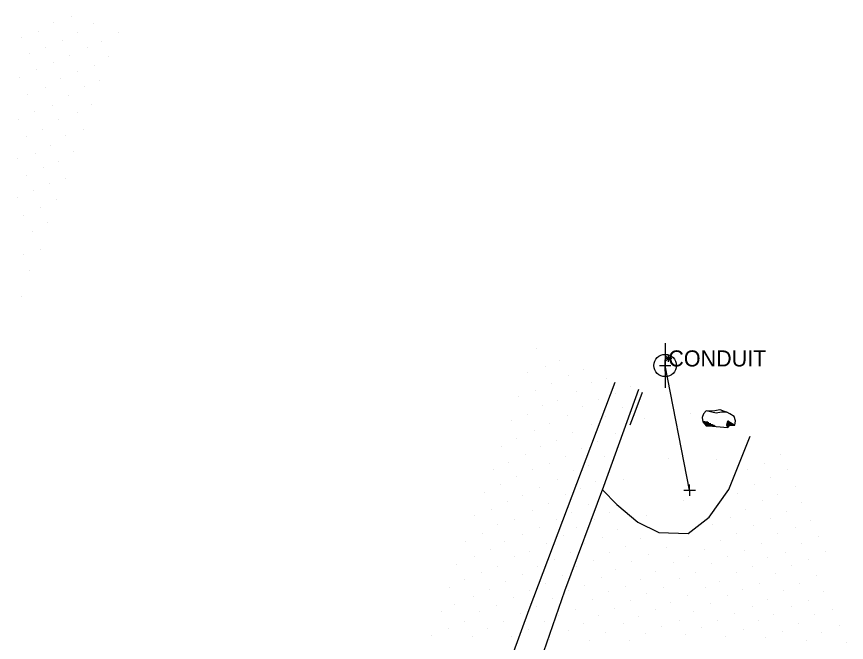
# Model space of a CAD drawing. Extents: x 1729983 to 1730242, y 468641 to 469019.
# Drawn here: x 1730133.1 to 1730225.9, y 468949.2 to 469019.2 of the extents above; entities that cross this region are included whole.
import ezdxf

# ---------------------------------------------------------------- set-up
doc = ezdxf.new("R2010")
doc.units = 0
for name, color, linetype in [('Default', 7, 'Continuous'), ('S_Curb_Type_1', 7, 'Continuous'), ('S_Ground_SpotElevation', 7, 'Continuous'), ('S_Misc_MiscItems', 7, 'Continuous'), ('S_Property_RockBoulder', 7, 'Continuous'), ('S_Roadway_Drive_Paved', 7, 'Continuous'), ('S_Roadway_Edge_Pavement', 7, 'Continuous'), ('S_Roadway_Painted_Lines', 7, 'Continuous'), ('S_Survey_Shot', 7, 'Continuous'), ('S_Text', 7, 'Continuous'), ('S_Utilities_GuyWire3', 7, 'Continuous'), ('S_Utilities_Pole_Power', 7, 'Continuous')]:
    doc.layers.add(name, color=color, linetype=linetype)

# ---------------------------------------------------------------- blocks, each defined once
blk = doc.blocks.new('POINT_DISPLAY')
at = {"layer": 'Default'}
blk.add_line((0, 0), (0, 0), dxfattribs=at)

msp = doc.modelspace()

# ---------------------------------------------------------------- linework, layer by layer
at = {"layer": 'S_Curb_Type_1'}
msp.add_lwpolyline([(1730201.693, 468973.575), (1730202.263, 468975.004), (1730203.086, 468977.205)], dxfattribs=at)
at = {"layer": 'S_Misc_MiscItems'}
for p, q in [((1730206.362, 468980.991), (1730205.576, 468980.991)), ((1730206.231, 468980.729), (1730205.707, 468981.253)), ((1730206.231, 468981.253), (1730205.707, 468980.729)), ((1730205.969, 468981.384), (1730205.969, 468980.598))]:
    msp.add_line(p, q, dxfattribs=at)
at = {"layer": 'S_Property_RockBoulder'}
for p, q in [((1730209.957, 468973.912), (1730210.387, 468973.912)), ((1730209.99, 468973.953), (1730209.99, 468973.83)), ((1730210.038, 468973.823), (1730210.505, 468973.823)), ((1730210.086, 468973.946), (1730210.086, 468973.685)), ((1730210.128, 468973.707), (1730210.732, 468973.707)), ((1730210.189, 468973.59), (1730210.903, 468973.59)), ((1730210.203, 468973.946), (1730210.203, 468973.576)), ((1730210.279, 468973.48), (1730211.123, 468973.48)), ((1730210.326, 468973.946), (1730210.326, 468973.432)), ((1730210.438, 468973.858), (1730210.438, 468973.439)), ((1730210.533, 468973.747), (1730210.533, 468973.452)), ((1730210.642, 468973.727), (1730210.642, 468973.432)), ((1730210.76, 468973.637), (1730210.76, 468973.432)), ((1730210.862, 468973.603), (1730210.862, 468973.405)), ((1730211.013, 468973.548), (1730211.013, 468973.405)), ((1730211.137, 468973.487), (1730211.137, 468973.425)), ((1730212.536, 468973.535), (1730212.64, 468973.727)), ((1730212.536, 468973.535), (1730212.64, 468973.582)), ((1730212.536, 468973.535), (1730212.64, 468973.527)), ((1730212.536, 468973.535), (1730212.64, 468973.432)), ((1730212.64, 468974.008), (1730212.852, 468973.535)), ((1730212.64, 468974.008), (1730213.29, 468973.535)), ((1730212.64, 468974.008), (1730213.119, 468973.535)), ((1730212.64, 468974.008), (1730212.955, 468973.535)), ((1730212.64, 468974.008), (1730212.792, 468973.463)), ((1730212.64, 468974.008), (1730212.753, 468973.414)), ((1730212.64, 468974.008), (1730212.64, 468973.274))]:
    msp.add_line(p, q, dxfattribs=at)
for points in [[(1730210.216, 468975.119), (1730211.164, 468975.168), (1730211.741, 468975.278), (1730212.536, 468974.962)], [(1730210.477, 468973.432), (1730212.64, 468973.274), (1730212.852, 468973.535), (1730213.429, 468973.535), (1730213.484, 468974.008), (1730213.325, 468974.481), (1730212.852, 468974.797), (1730212.536, 468974.962), (1730211.904, 468974.962), (1730211.321, 468974.852), (1730210.848, 468974.962), (1730210.216, 468975.119), (1730209.902, 468974.797), (1730209.743, 468974.379), (1730209.847, 468973.905), (1730210.216, 468973.432), (1730210.477, 468973.432)], [(1730212.64, 468973.274), (1730212.536, 468973.535), (1730212.64, 468974.008), (1730213.429, 468973.535)]]:
    msp.add_lwpolyline(points, dxfattribs=at)
at = {"layer": 'S_Roadway_Drive_Paved'}
msp.add_lwpolyline([(1730198.596, 468966.276), (1730200.222, 468964.652), (1730202.566, 468962.674), (1730204.922, 468961.527), (1730208.207, 468961.4), (1730210.542, 468963.235), (1730212.73, 468966.337), (1730215.136, 468972.288)], dxfattribs=at)
at = {"layer": 'S_Roadway_Edge_Pavement'}
msp.add_lwpolyline([(1730202.631, 468977.503), (1730198.74, 468966.662), (1730194.376, 468954.956), (1730192.027, 468948.149), (1730189.862, 468942.05), (1730183.636, 468926), (1730174.834, 468902.219), (1730173.778, 468899.255), (1730172.823, 468896.553), (1730172.2, 468894.754), (1730169.443, 468886.971), (1730164.503, 468873.715)], dxfattribs=at)
at = {"layer": 'S_Roadway_Painted_Lines'}
msp.add_lwpolyline([(1730094.799, 468656.256), (1730095.17, 468660.96), (1730096.083, 468669.985), (1730097.638, 468680.767), (1730099.581, 468691.95), (1730101.134, 468699.687), (1730104.772, 468714.073), (1730108.651, 468727.01), (1730112.542, 468738.83), (1730119.789, 468759.429), (1730137.203, 468807.807), (1730148.896, 468839.717), (1730160.486, 468871.271), (1730175.799, 468912.851), (1730190.41, 468952.883), (1730200.037, 468978.351)], dxfattribs=at)
at = {"layer": 'S_Survey_Shot'}
for p, q in [((1730205.619, 468979.565), (1730205.617, 468980.837)), ((1730204.982, 468980.2), (1730206.254, 468980.202)), ((1730205.618, 468980.201), (1730205.618, 468980.201)), ((1730208.361, 468965.624), (1730208.359, 468966.896)), ((1730207.724, 468966.259), (1730208.996, 468966.261)), ((1730208.36, 468966.26), (1730208.36, 468966.26))]:
    msp.add_line(p, q, dxfattribs=at)
at = {"layer": 'S_Utilities_GuyWire3'}
msp.add_lwpolyline([(1730208.36, 468966.26), (1730205.618, 468980.201)], dxfattribs=at)
at = {"layer": 'S_Utilities_Pole_Power'}
msp.add_line((1730205.618, 468982.696), (1730205.618, 468977.706), dxfattribs=at)
msp.add_circle((1730205.618, 468980.201), 1.248, dxfattribs=at)

# ---------------------------------------------------------------- block references
at = {"layer": 'S_Ground_SpotElevation'}
for p in [(1730139.207, 469019.242), (1730137.209, 469018.551), (1730141.654, 469018.42), (1730135.493, 469017.571), (1730139.866, 469017.469), (1730144.513, 469017.475), (1730133.575, 469016.937), (1730138.181, 469016.543), (1730142.598, 469016.432), (1730136.29, 469015.819), (1730140.962, 469015.812), (1730134.458, 469015.091), (1730139.017, 469014.92), (1730143.314, 469014.745), (1730135.278, 469013.283), (1730137.186, 469014.149), (1730141.791, 469013.809), (1730133.45, 469012.392), (1730139.883, 469013.123), (1730137.957, 469012.3), (1730140.652, 469011.399), (1730142.378, 469012.088), (1730134.32, 469010.53), (1730136.338, 469011.315), (1730138.88, 469010.384), (1730137.118, 469009.317), (1730141.416, 469009.4), (1730133.275, 469007.708), (1730135.075, 469008.571), (1730137.802, 469007.776), (1730139.867, 469008.493), (1730134.229, 469005.828), (1730135.963, 469006.658), (1730138.592, 469005.927), (1730140.54, 469006.57), (1730135.159, 469003.976), (1730136.846, 469004.848), (1730139.465, 469004.149), (1730133.157, 469003.359), (1730137.722, 469003.065), (1730136.052, 469002.317), (1730134.128, 469001.463), (1730136.754, 469000.594), (1730138.539, 469001.176), (1730134.949, 468999.744), (1730133.117, 468998.956), (1730137.543, 468998.786), (1730135.738, 468997.926), (1730133.851, 468997.012), (1730136.578, 468996.219), (1730134.798, 468995.159), (1730135.701, 468993.196), (1730133.829, 468992.578), (1730134.562, 468990.793), (1730133.569, 468987.92), (1730191.187, 468982.08), (1730193.833, 468980.769), (1730192.201, 468980.139), (1730190.235, 468979.389), (1730194.784, 468979.058), (1730196.535, 468979.751), (1730192.931, 468978.202), (1730197.399, 468978.296), (1730199.063, 468978.788), (1730191.104, 468977.433), (1730195.698, 468977.244), (1730200.095, 468977.11), (1730201.712, 468977.848), (1730189.222, 468976.691), (1730193.619, 468976.3), (1730198.196, 468976.419), (1730191.895, 468975.712), (1730196.421, 468975.629), (1730200.854, 468975.448), (1730190.249, 468974.73), (1730194.667, 468974.563), (1730198.977, 468974.543), (1730208.452, 468974.852), (1730188.396, 468974.062), (1730192.662, 468973.704), (1730197.363, 468973.598), (1730203.34, 468974.223), (1730191.014, 468972.918), (1730195.244, 468972.691), (1730200.02, 468972.627), (1730189.037, 468972.026), (1730193.495, 468971.794), (1730198.029, 468971.657), (1730187.275, 468971.11), (1730191.657, 468971.111), (1730196.206, 468970.884), (1730189.998, 468970.265), (1730194.48, 468970.042), (1730198.8, 468970.065), (1730205.964, 468969.752), (1730211.369, 468969.716), (1730218.469, 468970.254), (1730188.135, 468969.355), (1730192.705, 468969.282), (1730197.079, 468969.004), (1730216.75, 468969.231), (1730186.451, 468968.556), (1730188.952, 468967.805), (1730190.732, 468968.606), (1730195.343, 468968.496), (1730214.78, 468968.617), (1730219.313, 468968.542), (1730187.163, 468966.932), (1730193.57, 468967.443), (1730197.82, 468967.267), (1730200.995, 468967.489), (1730217.41, 468967.672), (1730185.464, 468965.993), (1730191.533, 468966.543), (1730196.124, 468966.415), (1730215.615, 468966.829), (1730220.204, 468966.628), (1730189.661, 468965.701), (1730194.42, 468965.745), (1730207.724, 468965.146), (1730213.761, 468965.841), (1730216.486, 468965.049), (1730218.218, 468965.802), (1730186.152, 468964.087), (1730188.024, 468964.958), (1730192.534, 468964.769), (1730197.032, 468964.66), (1730220.899, 468964.842), (1730184.239, 468963.36), (1730190.734, 468963.991), (1730195.17, 468963.711), (1730199.356, 468963.751), (1730203.563, 468963.453), (1730212.953, 468963.179), (1730214.611, 468964.043), (1730219.14, 468963.848), (1730186.865, 468962.369), (1730188.738, 468963.009), (1730193.417, 468962.982), (1730197.713, 468963.012), (1730210.958, 468962.456), (1730215.479, 468962.317), (1730217.366, 468963.126), (1730221.837, 468962.846), (1730185.192, 468961.427), (1730191.555, 468962.055), (1730195.73, 468962.066), (1730200.256, 468961.808), (1730213.645, 468961.448), (1730218.143, 468961.413), (1730220.202, 468962.021), (1730183.311, 468960.501), (1730187.673, 468960.488), (1730189.711, 468961.258), (1730194.283, 468961.207), (1730198.649, 468960.984), (1730202.87, 468960.832), (1730211.8, 468960.622), (1730222.739, 468961.03), (1730186.137, 468959.582), (1730190.483, 468959.433), (1730192.304, 468960.251), (1730196.577, 468960.331), (1730201.18, 468959.926), (1730205.74, 468959.816), (1730210.037, 468959.656), (1730214.486, 468959.523), (1730216.374, 468960.314), (1730220.829, 468960.324), (1730184.347, 468958.836), (1730188.717, 468958.807), (1730195.004, 468959.261), (1730199.388, 468959.22), (1730203.794, 468959.05), (1730208.225, 468958.809), (1730212.613, 468958.84), (1730217.116, 468958.704), (1730219.026, 468959.314), (1730223.543, 468959.348), (1730182.302, 468957.975), (1730186.84, 468957.699), (1730191.354, 468957.712), (1730193.253, 468958.475), (1730195.702, 468957.697), (1730197.645, 468958.347), (1730201.878, 468958.214), (1730206.515, 468958.122), (1730210.854, 468958.039), (1730215.442, 468957.677), (1730219.77, 468957.79), (1730221.646, 468958.474), (1730185.085, 468957.028), (1730189.627, 468956.832), (1730194.103, 468956.684), (1730200.056, 468957.342), (1730204.564, 468957.145), (1730209.007, 468957.05), (1730213.563, 468956.989), (1730217.999, 468956.898), (1730222.547, 468956.663), (1730183.205, 468956.266), (1730187.742, 468956.01), (1730192.198, 468955.799), (1730198.467, 468956.466), (1730202.837, 468956.279), (1730207.24, 468956.314), (1730211.714, 468956.002), (1730216.209, 468955.861), (1730220.699, 468955.86), (1730181.463, 468955.309), (1730185.943, 468955.104), (1730190.479, 468955.03), (1730194.779, 468955.013), (1730196.645, 468955.618), (1730199.242, 468954.87), (1730201.168, 468955.465), (1730205.422, 468955.409), (1730210.114, 468955.324), (1730214.315, 468955.158), (1730218.857, 468954.973), (1730223.35, 468954.949), (1730184.124, 468954.318), (1730188.681, 468954.281), (1730193.043, 468954.11), (1730197.508, 468953.993), (1730201.746, 468953.883), (1730203.528, 468954.708), (1730208.1, 468954.449), (1730212.562, 468954.462), (1730217.015, 468954.029), (1730221.629, 468953.876), (1730182.095, 468953.457), (1730186.792, 468953.31), (1730191.265, 468953.217), (1730195.606, 468952.935), (1730199.974, 468953.018), (1730206.219, 468953.624), (1730210.644, 468953.543), (1730215.346, 468953.214), (1730219.712, 468953.267), (1730180.555, 468952.656), (1730184.873, 468952.693), (1730189.426, 468952.488), (1730193.718, 468952.186), (1730198.129, 468952.246), (1730202.62, 468952.115), (1730204.541, 468952.873), (1730208.839, 468952.622), (1730213.345, 468952.462), (1730217.79, 468952.293), (1730222.28, 468952.344), (1730224.357, 468952.902), (1730183.158, 468951.599), (1730187.58, 468951.567), (1730192.134, 468951.509), (1730196.483, 468951.34), (1730200.912, 468951.35), (1730207.189, 468951.704), (1730211.486, 468951.665), (1730216.05, 468951.649), (1730220.487, 468951.293), (1730225.138, 468951.107), (1730181.376, 468950.788), (1730185.747, 468950.824), (1730190.352, 468950.64), (1730194.772, 468950.493), (1730198.97, 468950.338), (1730203.385, 468950.195), (1730205.19, 468950.991), (1730207.884, 468950.135), (1730209.724, 468950.842), (1730214.38, 468950.634), (1730218.725, 468950.389), (1730223.109, 468950.316), (1730179.494, 468949.935), (1730184.046, 468949.911), (1730188.414, 468949.924), (1730192.649, 468949.552), (1730197.134, 468949.416), (1730201.578, 468949.404), (1730212.415, 468949.898), (1730216.823, 468949.75), (1730221.414, 468949.455), (1730225.893, 468949.237)]:
    msp.add_blockref('POINT_DISPLAY', p, dxfattribs=at)

# ---------------------------------------------------------------- texts
at = {"layer": 'S_Text'}
msp.add_text('CONDUIT', height=1.8, dxfattribs=at).set_placement((1730205.969, 468980.091))

doc.saveas('drawing.dxf')
